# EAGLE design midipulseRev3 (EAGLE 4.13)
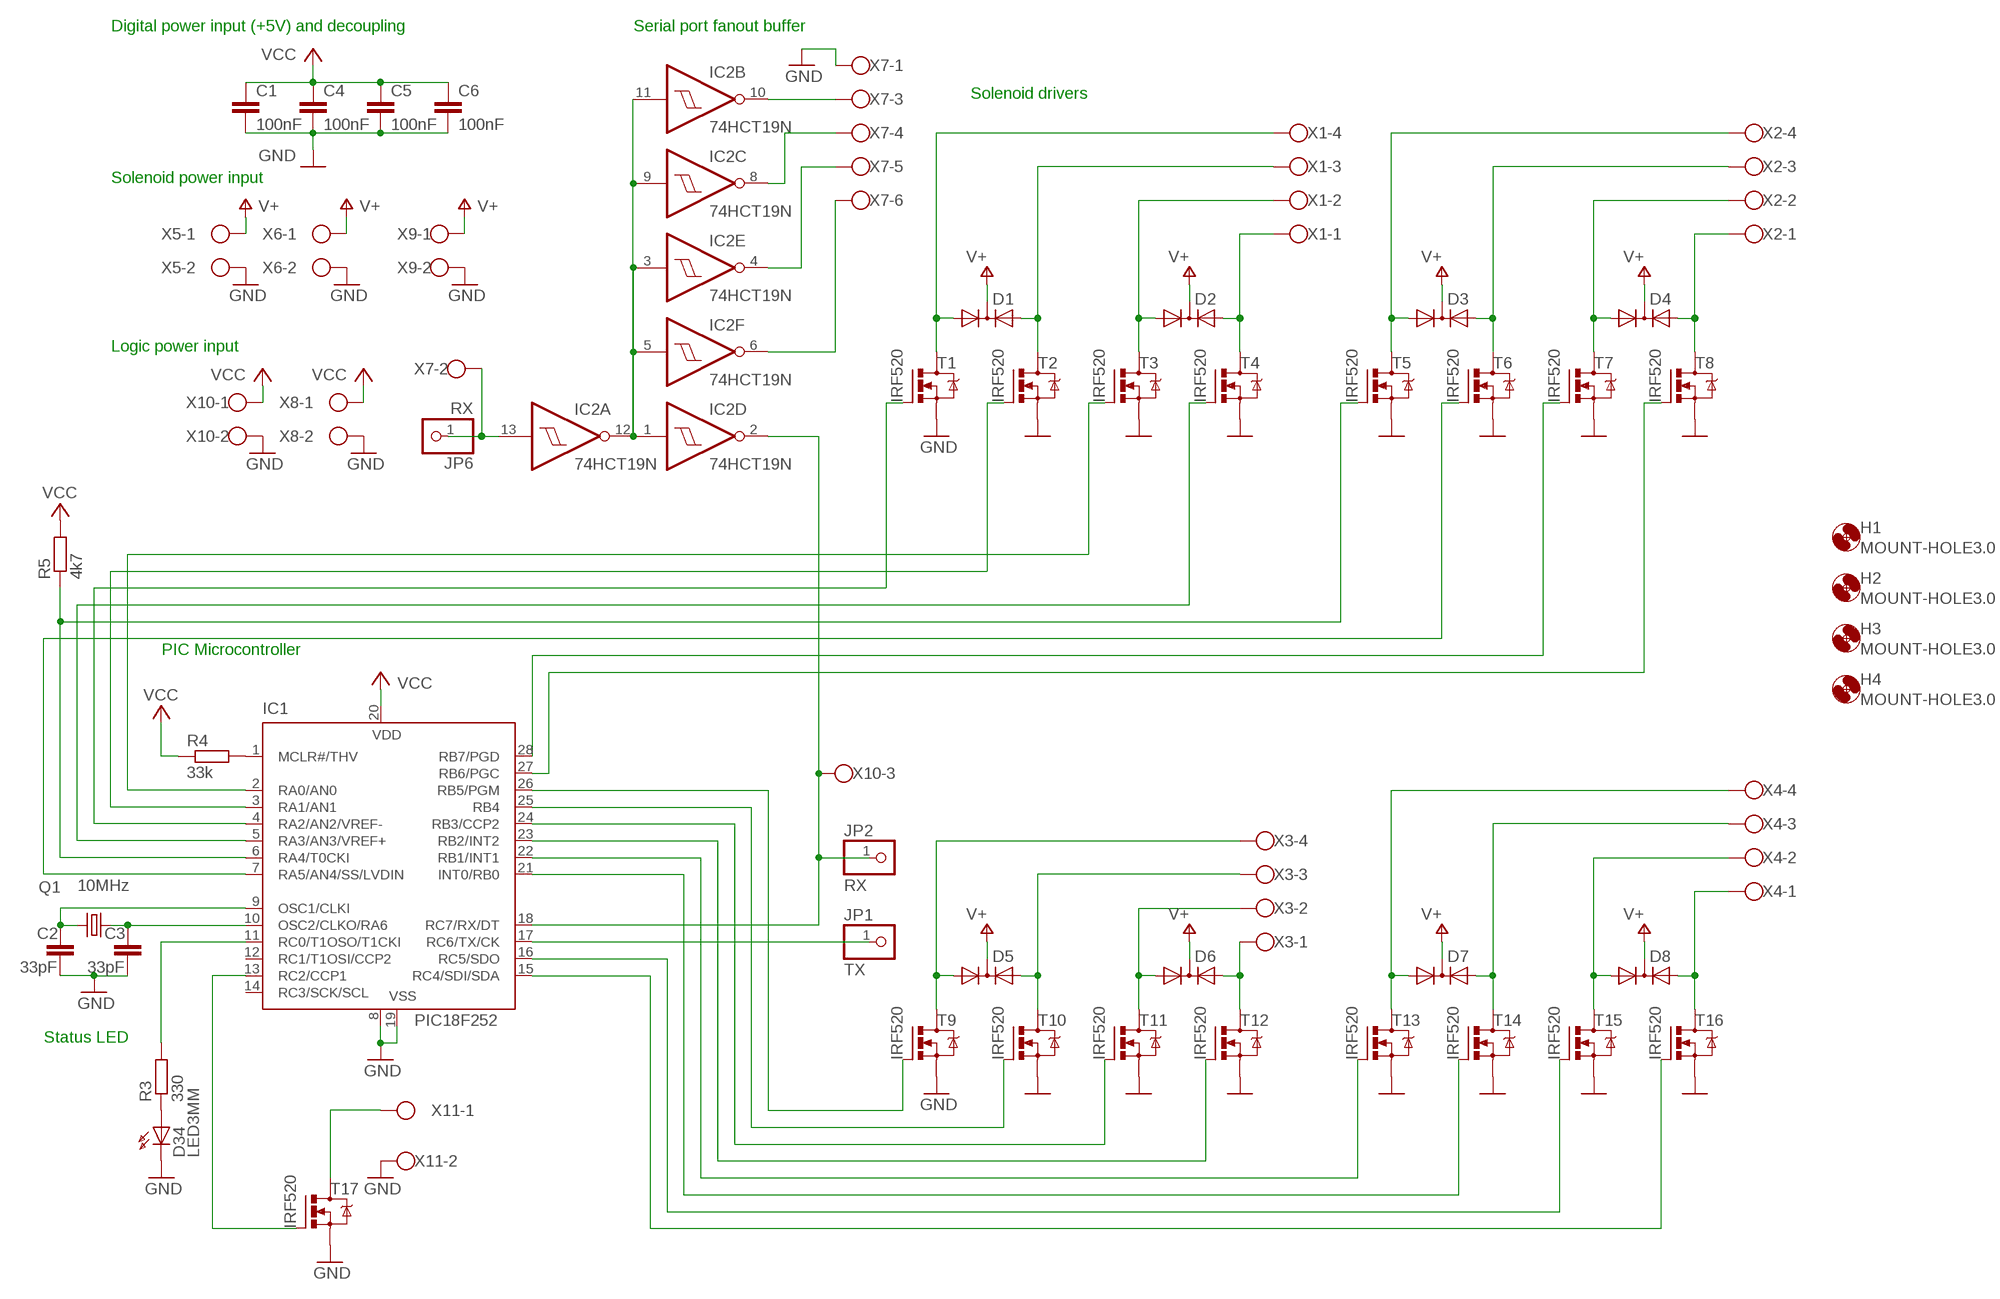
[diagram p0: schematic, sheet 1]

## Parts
C1  100nF  C-EU050-030X075  [C050-030X075]
C2  33pF  C-EU050-025X075  [C050-025X075]
C3  33pF  C-EU050-025X075  [C050-025X075]
C4  100nF  C-EU050-030X075  [C050-030X075]
C5  100nF  C-EU050-030X075  [C050-030X075]
C6  100nF  C-EU050-030X075  [C050-030X075]
D1  DIODE-2AC|CATO220V  [TO220ABS]
D2  DIODE-2AC|CATO220V  [TO220ABS]
D3  DIODE-2AC|CATO220V  [TO220ABS]
D4  DIODE-2AC|CATO220V  [TO220ABS]
D5  DIODE-2AC|CATO220V  [TO220ABS]
D6  DIODE-2AC|CATO220V  [TO220ABS]
D7  DIODE-2AC|CATO220V  [TO220ABS]
D8  DIODE-2AC|CATO220V  [TO220ABS]
D34  LED3MM  [LED3MM]
H1  MOUNT-HOLE3.0  [3,0]
H2  MOUNT-HOLE3.0  [3,0]
H3  MOUNT-HOLE3.0  [3,0]
H4  MOUNT-HOLE3.0  [3,0]
IC1  PIC18F252  [DIL28-3]
IC2  74HCT19N  [DIL14]
JP1  TX  PINHD-1X1  [1X01]
JP2  RX  PINHD-1X1  [1X01]
JP6  RX  PINHD-1X1  [1X01]
Q1  10MHz  HC49U70  [HC49U70]
R3  330  R-EU_0207/7  [0207/7]
R4  33k  R-EU_0207/10  [0207/10]
R5  4k7  R-EU_0207/10  [0207/10]
T1  IRF520  [TO220BV-ROUND]
T2  IRF520  [TO220BV-ROUND]
T3  IRF520  [TO220BV-ROUND]
T4  IRF520  [TO220BV-ROUND]
T5  IRF520  [TO220BV-ROUND]
T6  IRF520  [TO220BV-ROUND]
T7  IRF520  [TO220BV-ROUND]
T8  IRF520  [TO220BV-ROUND]
T9  IRF520  [TO220BV-ROUND]
T10  IRF520  [TO220BV-ROUND]
T11  IRF520  [TO220BV-ROUND]
T12  IRF520  [TO220BV-ROUND]
T13  IRF520  [TO220BV-ROUND]
T14  IRF520  [TO220BV-ROUND]
T15  IRF520  [TO220BV-ROUND]
T16  IRF520  [TO220BV-ROUND]
T17  IRF520  [TO220BV-ROUND]
X1  W237-04P  [W237-4P]
X2  W237-04P  [W237-4P]
X3  W237-04P  [W237-4P]
X4  W237-04P  [W237-4P]
X5  W237-02P  [W237-132]
X6  W237-02P  [W237-132]
X7  W237-06P  [W237-6P]
X8  W237-02P  [W237-132]
X9  W237-02P  [W237-132]
X10  W237-03P  [W237-133]
X11  W237-02P  [W237-132]

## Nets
GND: C1.2 C2.2 C3.2 C4.2 C5.2 C6.2 D34.K(C) IC1.8(VSS) IC1.19(VSS) T1.S T2.S T3.S T4.S T5.S T6.S T7.S T8.S T9.S T10.S T11.S T12.S T13.S T14.S T15.S T16.S T17.S X5.2 X6.2 X7.1 X8.2 X9.2 X10.2 X11.2
N$1: D5.A2 T10.D X3.3
N$2: D5.A1 T9.D X3.4
N$3: C2.1 IC1.9(OSC1/CLKI) Q1.1
N$4: C3.1 IC1.10(OSC2/CLKO/RA6) Q1.2
N$5: D1.A2 T2.D X1.3
N$6: D1.A1 T1.D X1.4
N$7: IC1.1(MCLR#/THV) R4.2
N$8: IC2.1(D:I) IC2.3(E:I) IC2.5(F:I) IC2.9(C:I) IC2.11(B:I) IC2.12(A:O)
N$9: IC2.10(B:O) X7.3
N$10: D6.A2 T12.D X3.1
N$11: IC1.2(RA0/AN0) T3.G
N$13: D6.A1 T11.D X3.2
N$14: D2.A2 T4.D X1.1
N$15: IC1.3(RA1/AN1) T2.G
N$16: IC1.6(RA4/T0CKI) R5.1 T5.G
N$17: IC2.6(F:O) X7.6
N$18: IC2.4(E:O) X7.5
N$19: IC2.8(C:O) X7.4
N$20: D7.A2 T14.D X4.3
N$21: D2.A1 T3.D X1.2
N$22: IC1.4(RA2/AN2/VREF-) T1.G
N$23: D7.A1 T13.D X4.4
N$24: D3.A2 T6.D X2.3
N$25: IC1.5(RA3/AN3/VREF+) T4.G
N$26: D8.A2 T16.D X4.1
N$27: D3.A1 T5.D X2.4
N$28: IC1.28(RB7/PGD) T7.G
N$29: D8.A1 T15.D X4.2
N$30: D4.A2 T8.D X2.1
N$31: IC1.7(RA5/AN4/SS/LVDIN) T6.G
N$32: T17.D X11.1
N$33: D4.A1 T7.D X2.2
N$34: IC1.26(RB5/PGM) T9.G
N$35: IC1.13(RC2/CCP1) T17.G
N$37: IC1.27(RB6/PGC) T8.G
N$40: IC1.16(RC5/SDO) T15.G
N$43: IC1.25(RB4) T10.G
N$44: IC2.13(A:I) JP6.1 X7.2
N$46: IC1.24(RB3/CCP2) T11.G
N$49: IC1.23(RB2/INT2) T12.G
N$52: IC1.22(RB1/INT1) T13.G
N$55: IC1.21(INT0/RB0) T14.G
N$61: IC1.15(RC4/SDI/SDA) T16.G
N$62: IC1.18(RC7/RX/DT) IC2.2(D:O) JP2.1 X10.3
N$64: D34.A R3.1
N$65: IC1.17(RC6/TX/CK) JP1.1
N$66: IC1.11(RC0/T1OSO/T1CKI) R3.2
V+: D1.C D2.C D3.C D4.C D5.C D6.C D7.C D8.C X5.1 X6.1 X9.1
VCC: C1.1 C4.1 C5.1 C6.1 IC1.20(VDD) R4.1 R5.2 X8.1 X10.1
Unconnected: IC1.12(RC1/T1OSI/CCP2) IC1.14(RC3/SCK/SCL)

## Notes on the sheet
- Digital power input (+5V) and decoupling | Serial port fanout buffer
- Solenoid drivers
- Solenoid power input
- Logic power input
- PIC Microcontroller
- Status LED

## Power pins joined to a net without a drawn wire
GND: IC2.7(P:GND)
VCC: IC2.14(P:VCC)

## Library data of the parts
C1-C6 = rcl:C-EU: CAPACITOR, European symbol
D1-D8 = diode:DIODE-2AC|CA: Dual DIODE Anode-Cathode|Cathode-Anode
D34 = led:LED3MM: LED
H1-H4 = holes:MOUNT-HOLE: MOUNTING HOLE with drill center marker
IC1 = microchip:PIC18F252
IC2 = 74xx-eu:74*19: Hex schmitt trigger INVERTER
JP1 JP2 JP6 = pinhead:PINHD-1X1: PIN HEADER
Q1 = crystal:HC49U70: CRYSTAL
R3-R5 = rcl:R-EU_: RESISTOR, European symbol
T1-T17 = transistor-power:IRF520: HEXFET Power MOSFET
X1-X4 = con-wago-508:W237-04P: WAGO SREW CLAMP
X5 X6 X8 X9 X11 = con-wago-508:W237-02P: WAGO SREW CLAMP
X7 = con-wago-508:W237-06P: WAGO SREW CLAMP
X10 = con-wago-508:W237-03P: WAGO SREW CLAMP

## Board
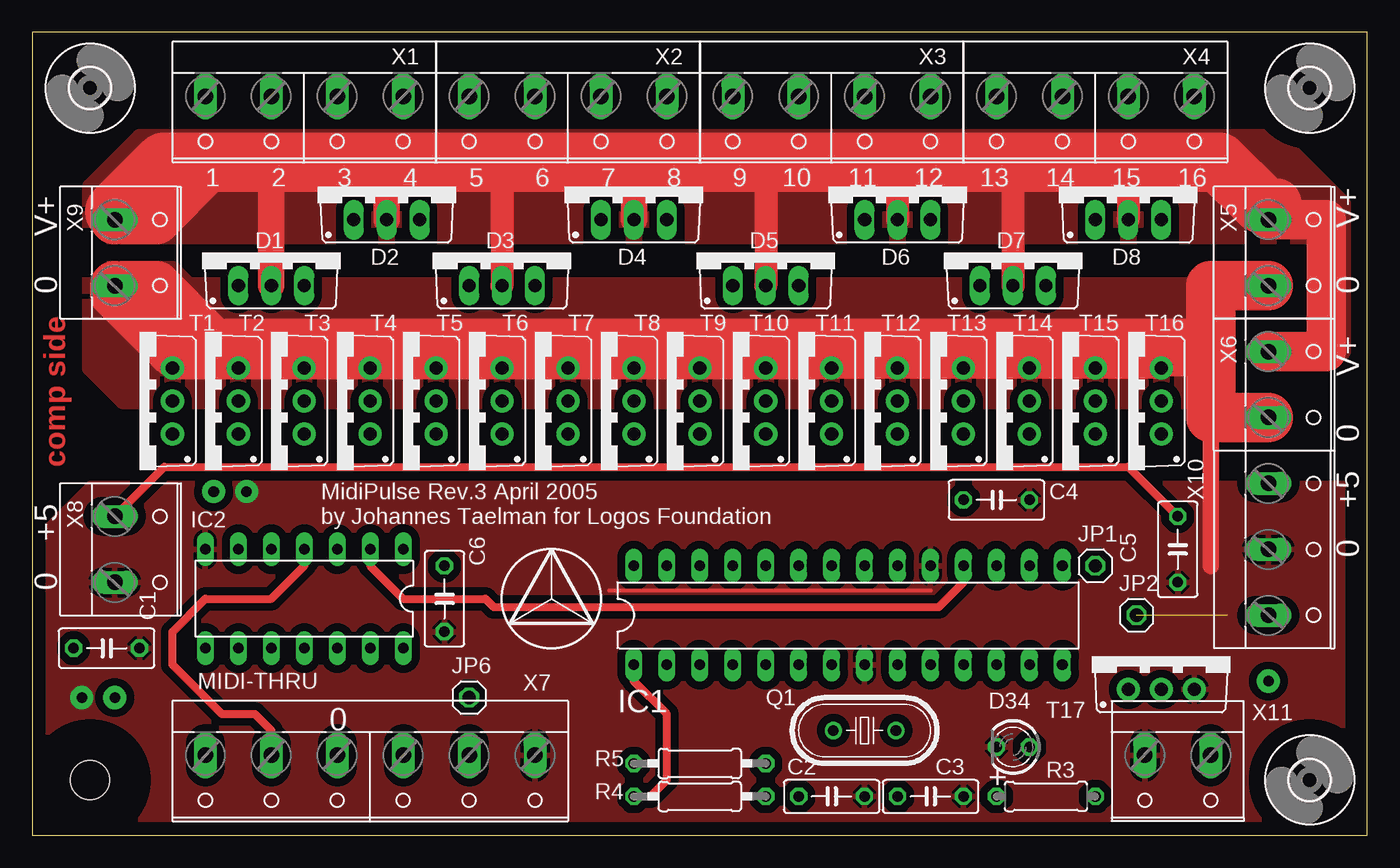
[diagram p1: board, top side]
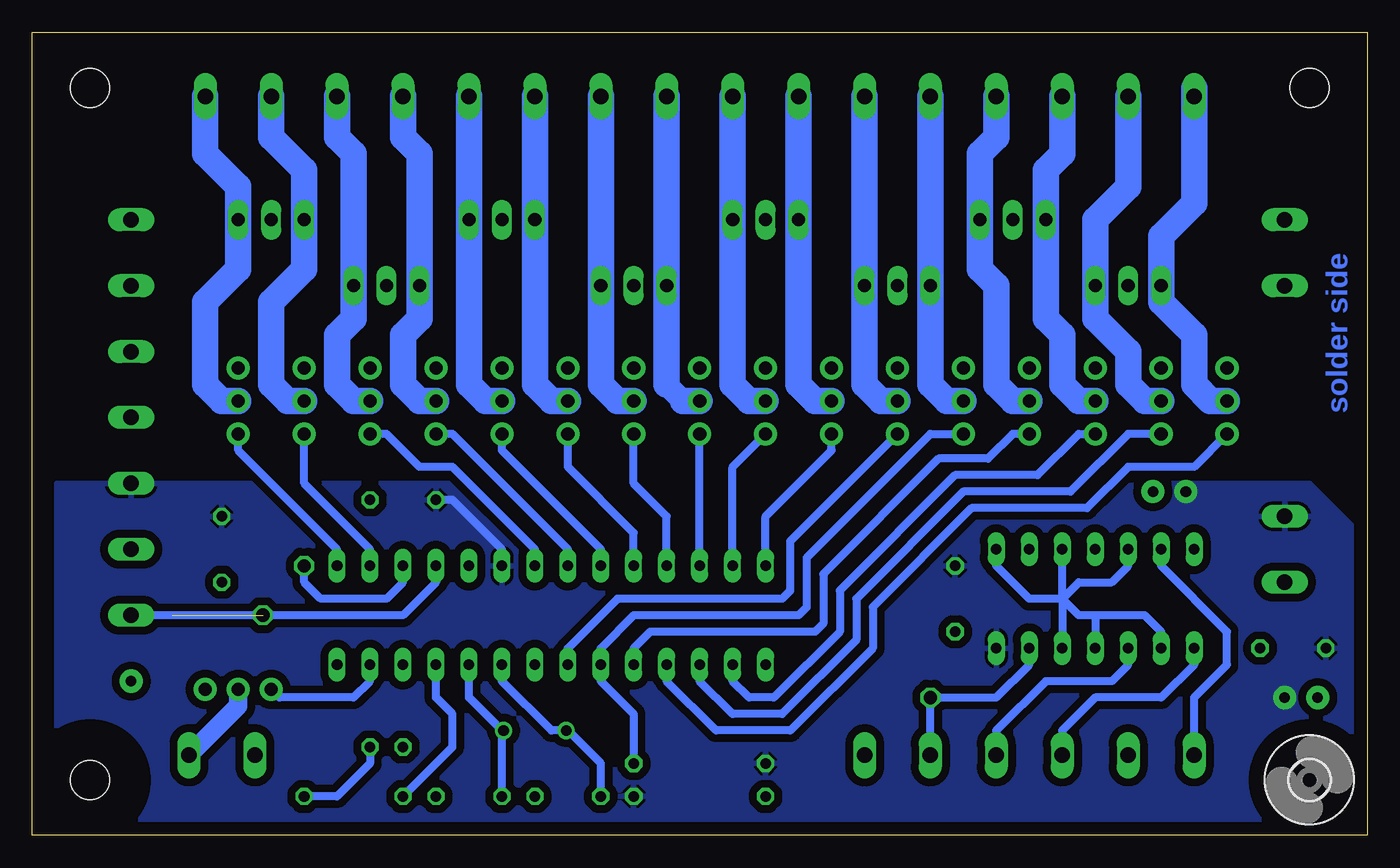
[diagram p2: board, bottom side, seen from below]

Size 102.85 x 61.9 mm. Coordinates in mm from the lower left corner, seen from the top.
Outline: 0,0 102.85,0 102.85,61.9 0,61.9 0,0
Copper layers (1*16): Top 0.035mm / dielectric 1.5mm / Bottom 0.035mm
Design rules "default": minimum track width 10mil, minimum drill 24mil, track to track 8mil, track to pad 8mil, pad to pad 8mil, via to via 8mil, smd to smd 8mil, copper to edge 40mil, drill to drill 8mil, minimum pad ring 10mil, minimum via ring 8mil, stop-mask expansion 0mil, vias tented up to drill 0mil, thermal gap 10mil

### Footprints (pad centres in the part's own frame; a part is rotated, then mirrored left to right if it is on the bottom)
C050-030X075 = drill 0.813 octagon: 1 -2.54,0; 2 2.54,0
C050-025X075 = drill 0.813 octagon: 1 -2.54,0; 2 2.54,0
TO220ABS = drill 1.016 long: A1 -2.54,-2.54; A2 2.54,-2.54; C 0,-2.54
LED3MM@1 = drill 0.813 octagon: A -1.27,0; K 1.27,0
3,0 = hole 3: 0,0
DIL28-3 = drill 0.813 long: 1 -16.51,-3.81; 2 -13.97,-3.81; 3 -11.43,-3.81; 4 -8.89,-3.81; 5 -6.35,-3.81; 6 -3.81,-3.81; 7 -1.27,-3.81; 8 1.27,-3.81; 9 3.81,-3.81; 10 6.35,-3.81; 11 8.89,-3.81; 12 11.43,-3.81; 13 13.97,-3.81; 14 16.51,-3.81; 15 16.51,3.81; 16 13.97,3.81; 17 11.43,3.81; 18 8.89,3.81; 19 6.35,3.81; 20 3.81,3.81; 21 1.27,3.81; 22 -1.27,3.81; 23 -3.81,3.81; 24 -6.35,3.81; 25 -8.89,3.81; 26 -11.43,3.81; 27 -13.97,3.81; 28 -16.51,3.81
DIL14 = drill 0.813 long: 1 -7.62,-3.81; 2 -5.08,-3.81; 3 -2.54,-3.81; 4 0,-3.81; 5 2.54,-3.81; 6 5.08,-3.81; 7 7.62,-3.81; 8 7.62,3.81; 9 5.08,3.81; 10 2.54,3.81; 11 0,3.81; 12 -2.54,3.81; 13 -5.08,3.81; 14 -7.62,3.81
1X01 = drill 1.016 octagon: 1 0,0
HC49U70@1 = drill 0.813 round: 1 -2.413,0; 2 2.413,0
0207/7 = drill 0.813 octagon: 1 -3.81,0; 2 3.81,0
0207/10 = drill 0.813 octagon: 1 -5.08,0; 2 5.08,0
TO220BV-ROUND = drill 1.016 pad 1.778 round: D 0,-2.54; G -2.54,-2.54; S 2.54,-2.54
W237-4P = drill 1.194 long: 1 -7.62,-0.635; 2 -2.54,-0.635; 3 2.54,-0.635; 4 7.62,-0.635
W237-132 = drill 1.194 long: 1 -2.54,-0.635; 2 2.54,-0.635
W237-6P = drill 1.194 long: 1 -12.7,-0.635; 2 -7.62,-0.635; 3 -2.54,-0.635; 4 2.54,-0.635; 5 7.62,-0.635; 6 12.7,-0.635
W237-133 = drill 1.194 long: 1 -5.08,-0.635; 2 0,-0.635; 3 5.08,-0.635

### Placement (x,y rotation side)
C1  5.71,14.44 0 top
C2  61.59,3.01 0 top
C3  69.21,3.01 0 top
C4  74.29,25.87 0 top
C5  88.26,22.06 270 top
C6  31.74,18.25 270 top
D1  18.41,44.92 0 top
D2  27.3,50 0 top
D3  36.19,44.92 0 top
D4  46.35,50 0 top
D5  56.51,44.92 0 top
D6  66.67,50 0 top
D7  75.56,44.92 0 top
D8  84.45,50 0 top
D34  LED3MM  [LED3MM@1]  75.56,6.82 180 top
H1  4.44,4.28 0 bottom
H2  98.42,4.28 0 top
H3  98.42,57.62 0 top
H4  4.44,57.62 0 top
IC1  62.86,16.98 0 top
IC2  20.95,18.25 180 top
JP1  81.91,20.79 0 top
JP2  85.08,16.98 0 top
JP6  33.65,10.63 0 top
Q1  10MHz  [HC49U70@1]  64.13,8.09 0 top
R3  78.1,3.01 180 top
R4  51.43,3.01 180 top
R5  51.43,5.55 180 top
T1  8.25,33.49 90 top
T2  13.33,33.49 90 top
T3  18.41,33.49 90 top
T4  23.49,33.49 90 top
T5  28.57,33.49 90 top
T6  33.65,33.49 90 top
T7  38.73,33.49 90 top
T8  43.81,33.49 90 top
T9  48.89,33.49 90 top
T10  53.97,33.49 90 top
T11  59.05,33.49 90 top
T12  64.13,33.49 90 top
T13  69.21,33.49 90 top
T14  74.29,33.49 90 top
T15  79.37,33.49 90 top
T16  84.45,33.49 90 top
T17  86.99,13.81 0 top
X1  20.95,56.35 180 top
X2  41.27,56.35 180 top
X3  61.59,56.35 180 top
X4  81.91,56.35 180 top
X5  95.88,44.92 270 top
X6  95.88,34.76 270 top
X7  26.03,5.55 180 top
X8  6.98,22.06 270 top
X9  6.98,44.92 270 top
X10  95.88,22.06 270 top
X11  88.26,5.55 180 top

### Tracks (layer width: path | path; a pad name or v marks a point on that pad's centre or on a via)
GND  (via drill 0.81 pad 1.78)
  Top 0.305: 44.45,18.88 69.21,18.88
  Top 1.27: T16.S 90.8,36.03 90.8,37.3 80.64,37.3 | 90.8,32.22 90.8,20.79 | 9.52,37.3 9.52,38.57
  Top 1.676: T1.S T2.S T3.S T4.S T5.S T6.S T7.S T8.S T9.S T10.S T11.S T12.S T13.S T14.S T15.S T16.S
  Top 1.778: 80.64,37.3 10.79,37.3 9.52,37.3 T1.S
  Top 2.54: 90.8,37.3 90.8,38.57 13.33,38.57 9.52,38.57
  Top 3.81: 6.98,42.38 9.52,42.38 13.33,38.57 | X5.2 90.8,42.38 90.8,38.57 | 90.8,37.3 90.8,32.22 X6.2 | X9.2 6.34,41.74 10.79,37.3
  other vias: 3.8,10.63 16.5,26.5
  pour Top (isolate 0.61): 0.63,23.33 4.44,27.14 100.96,27.14 100.96,0.47 0.63,0.47
  pour Top (isolate 0.61): 4.44,43.65 10.79,43.65 12.06,42.38 92.07,42.38 92.07,33.49 6.98,33.49 4.44,36.03
N$1
  Bottom 1.016: X3.3 59.05,57.62
  Bottom 2.032: T10.D 57.78,33.49 59.05,34.76 D5.A2 X3.3
N$2
  Bottom 1.016: X3.4 53.97,57.62
  Bottom 1.676: 52.7,33.49 53.97,34.76
  Bottom 2.032: T9.D 52.7,33.49 | X3.4 D5.A1 53.97,34.76
N$3
  Bottom 0.61: IC1.9 66.67,11.9 62.86,8.09 Q1.1 61.59,8.09 59.05,5.55 C2.1
N$4
  Bottom 0.61: 66.67,8.09 Q1.2 66.54,8.22 66.67,8.09 | IC1.10 69.21,10.63 66.67,8.09 | C3.1 66.67,8.09
N$5
  Bottom 1.016: X1.3 18.41,57.62
  Bottom 2.032: T2.D 17.14,33.49 18.41,34.76 18.41,37.3 20.95,39.84 D1.A2 20.95,47.46 18.41,50 X1.3
N$6
  Bottom 1.016: 13.33,57.62 X1.4
  Bottom 2.032: T1.D 12.06,33.49 13.33,34.76 13.33,38.57 15.87,41.11 D1.A1 15.87,46.19 13.33,48.73 13.33,57.62
N$7
  Top 0.61: R4.2 47.62,3.01 48.89,4.28 48.89,9.36 46.35,11.9 IC1.1
N$8
  Bottom 0.61: IC2.1 28.57,20.79 26.03,18.25 23.49,18.25 | 23.49,18.25 IC2.12 | 23.49,18.25 22.22,16.98 20.95,16.98 | 20.95,16.98 IC2.11 | 20.95,16.98 17.14,16.98 15.87,15.71 IC2.9 | 23.49,18.25 IC2.3 | 23.49,18.25 22.22,19.52 19.68,19.52 18.41,20.79 IC2.5
N$9
  Bottom 0.61: IC2.10 18.41,13.17 19.68,11.9 24.76,11.9 28.57,8.09 X7.3
N$10
  Bottom 1.016: X3.1 69.21,57.62
  Bottom 2.032: T12.D 67.94,33.49 69.21,34.76 D6.A2 X3.1
N$11
  Bottom 0.61: IC1.2 48.89,11.9 47.62,10.63 45.72,10.63 40.64,15.71 40.64,18.88 31.74,27.77 25.39,27.77 22.22,30.95 T3.G
N$13
  Bottom 1.016: X3.2 64.13,57.62
  Bottom 2.032: T11.D 62.86,33.49 64.13,34.76 D6.A1 X3.2
N$14
  Bottom 1.016: X1.1 28.57,57.62
  Bottom 2.032: T4.D 27.3,33.49 28.57,34.76 28.57,42.38 29.84,43.65 D2.A2 29.84,52.54 28.57,53.81 X1.1
N$15
  Bottom 0.61: IC1.3 51.43,11.9 48.89,9.36 45.08,9.36 39.37,15.08 39.37,18.25 31.11,26.5 22.86,26.5 18.41,30.95 T2.G
N$16
  Bottom 0.61: R5.1 56.51,9.36 59.05,11.9 IC1.6 59.05,14.44 56.51,16.98 43.81,16.98 43.18,17.61 43.18,21.42 33.65,30.95 T5.G
N$17
  Bottom 0.61: IC2.6 15.87,20.79 10.79,15.71 10.79,13.17 13.33,10.63 X7.6
N$18
  Top 0.61: IC2.4 20.95,20.79 18.41,18.25 13.33,18.25 10.79,15.71 10.79,13.17 14.6,9.36 17.14,9.36 18.41,8.09 X7.5
N$19
  Bottom 0.61: IC2.8 13.33,13.17 15.87,10.63 20.95,10.63 23.49,8.09 X7.4
N$20
  Bottom 1.016: X4.3 79.37,57.62
  Bottom 2.032: T14.D 78.1,33.49 79.37,34.76 79.37,38.57 78.1,39.84 D7.A2 78.1,52.54 79.37,53.81 X4.3
N$21
  Bottom 1.016: X1.2 23.49,57.62
  Bottom 2.032: T3.D 22.22,33.49 23.49,34.76 23.49,38.57 24.76,39.84 D2.A1 24.76,51.27 23.49,52.54 X1.2
N$22
  Bottom 0.61: IC1.4 53.97,11.9 50.16,8.09 44.45,8.09 38.1,14.44 38.1,17.61 30.47,25.23 21.58,25.23 18.41,28.41 13.33,28.41 T1.G
N$23
  Bottom 2.032: T13.D 73.02,33.49 74.29,34.76 74.29,38.57 73.02,39.84 D7.A1 73.02,52.54 74.29,53.81 X4.4
N$24
  Bottom 1.016: X2.3 38.73,57.62
  Bottom 2.032: T6.D 37.46,33.49 38.73,34.76 D3.A2 X2.3
N$25
  Bottom 0.61: IC1.5 56.51,14.44 55.24,15.71 42.54,15.71 41.91,16.34 41.91,20.15 33.02,29.04 29.2,29.04 27.3,30.95 T4.G
N$26
  Bottom 1.016: X4.1 89.53,57.62
  Bottom 2.032: T16.D 88.26,33.49 89.53,34.76 89.53,41.11 86.99,43.65 D8.A2 86.99,50 89.53,52.54 X4.1
N$27
  Bottom 1.016: X2.4 33.65,57.62
  Bottom 2.032: T5.D 32.38,33.49 33.65,34.76 D3.A1 X2.4
N$28
  Bottom 0.61: IC1.28 46.35,24.6 41.27,29.68 T7.G
N$29
  Bottom 1.016: X4.2 84.45,57.62
  Bottom 2.032: T15.D 83.18,33.49 84.45,34.76 84.45,41.11 81.91,43.65 D8.A1 81.91,51.27 84.45,53.81 X4.2
N$30
  Bottom 1.016: X2.1 48.89,57.62
  Bottom 2.032: T8.D 47.62,33.49 48.89,34.76 D4.A2 X2.1
N$31
  Bottom 0.61: IC1.7 61.59,14.44 57.78,18.25 45.08,18.25 44.45,18.88 44.45,22.7 T6.G
N$32
  Bottom 1.422: T17.D 86.99,10 X11.1
N$33
  Bottom 1.016: X2.2 43.81,57.62
  Bottom 2.032: T7.D 42.54,33.49 43.81,34.76 D4.A1 X2.2
N$34
  Bottom 0.61: IC1.26 T9.G
N$35
  Bottom 0.61: IC1.13 76.83,11.9 78.1,10.63 83.81,10.63 T17.G
N$37
  Bottom 0.61: IC1.27 48.89,28.41 T8.G
N$40
  Bottom 0.61: IC1.16 76.83,22.06 81.91,27.14 T15.G
N$43
  Bottom 0.61: IC1.25 53.97,24.6 56.51,27.14 T10.G
N$44
  Bottom 0.61: IC2.13 26.03,13.17 28.57,10.63 JP6.1 X7.2
N$46
  Bottom 0.61: IC1.24 56.51,23.33 61.59,28.41 T11.G
N$49
  Bottom 0.61: IC1.23 59.05,22.06 66.67,29.68 T12.G
N$52
  Bottom 0.61: IC1.22 61.59,22.06 70.48,30.95 T13.G
N$55
  Bottom 0.61: IC1.21 64.13,22.06 70.48,28.41 73.02,28.41 75.56,30.95 T14.G
N$61
  Bottom 0.61: IC1.15 79.37,22.06 86.99,29.68 T16.G
N$62  (1 unrouted)
  Top 0.61: IC2.2 26.03,20.79 28.57,18.25 34.92,18.25 35.55,17.61 69.84,17.61 71.75,19.52 IC1.18
  Bottom 0.61: IC1.18 71.75,19.52 74.29,16.98 92.07,16.98 X10.3
N$64
  Bottom 0.61: D34.A 76.83,5.55 79.37,3.01 R3.1
N$65
  Bottom 0.61: IC1.17 74.29,19.52 75.56,18.25 80.64,18.25 81.91,19.52 JP1.1
N$66
  Bottom 0.61: R3.2 70.48,6.82 70.48,9.36 71.75,10.63 IC1.11
N$68  (via drill 0.81 pad 1.78)
  other vias: 95.24,11.9
V+
  Top 1.778: 95.88,48.73 97.15,47.46 99.69,47.46 | 36.19,51.91 D3.C | 56.51,51.91 D5.C | 66.67,51.91 D6.C | 75.56,51.91 D7.C | 84.45,51.91 D8.C
  Top 2.032: 18.41,51.91 D1.C | 27.3,51.91 D2.C | 46.35,51.91 D4.C
  Top 3.048: X5.1 99.69,47.46 99.69,37.3 X6.1
  Top 3.81: 94.61,48.73 95.88,48.73 | X9.1 6.34,48.09 | 6.98,47.46 9.52,47.46 13.33,51.27
  Top 4.572: 94.61,48.73 91.44,51.91 84.45,51.91 75.56,51.91 66.67,51.91 56.51,51.91 46.35,51.91 36.19,51.91 27.3,51.91 18.41,51.91 10.16,51.91 6.34,48.09
  pour Top (isolate 0.61): 4.44,50 8.25,53.81 95.88,53.81 100.96,48.73 100.96,37.3 99.69,37.3 99.69,46.19 4.44,46.19
VCC  (via drill 0.81 pad 1.78)
  Top 0.61: X8.1 10.16,28.41 84.45,28.41 C5.1
  Bottom 0.61: IC1.20 66.67,22.06 70.48,25.87 C4.1
  other vias: 6.34,10.63 13.97,26.5
  pour Bottom (isolate 0.61): 0.63,23.33 4.44,27.14 100.96,27.14 100.96,0.47 0.63,0.47

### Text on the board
Top: comp side
Bottom: solder side
tNames: 1 | 2 | 3 | 4 | 5 | 6 | 7 | 8 | 9 | 10 | 11 | 12 | 13 | 14 | 15 | 16 | V+ | V+ | 0 | 0 | V+ | 0 | MidiPulse Rev.3 April 2005 | +5 | by Johannes Taelman for Logos Foundation | +5 | 0 | 0 | MIDI-THRU | 0 | +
